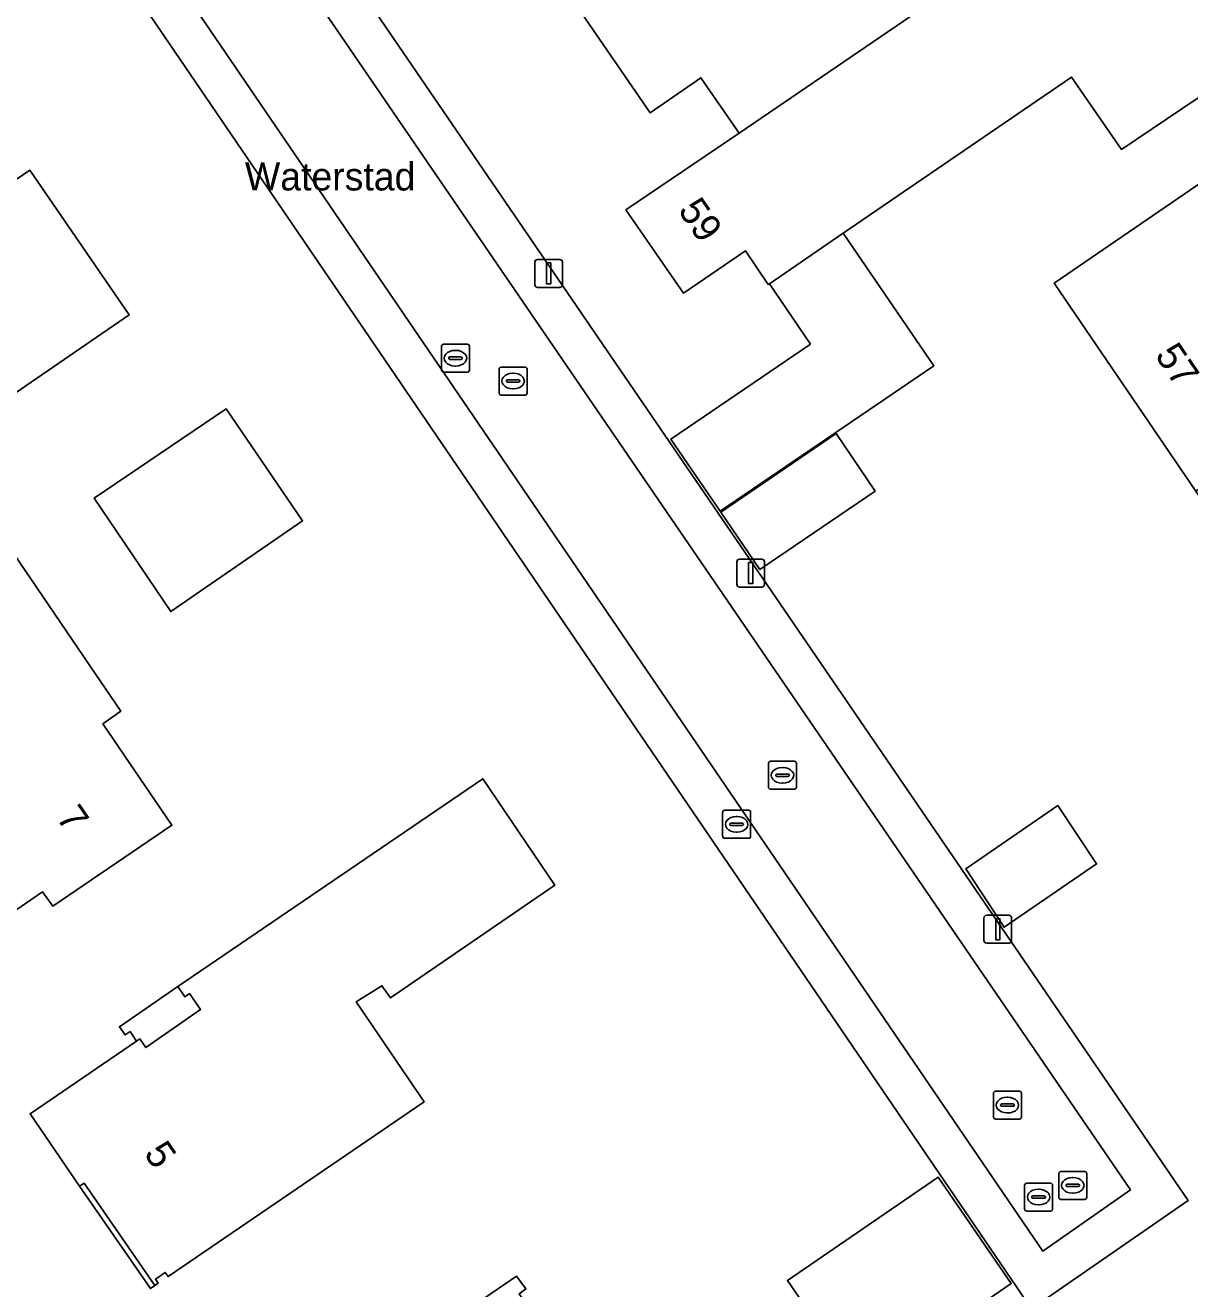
# Model space of a CAD drawing. Extents: x 155275 to 156265, y 382654 to 383635.
# Drawn here: x 155692.89 to 155734.53, y 383268.44 to 383313.6 of the extents above; entities that cross this region are included whole.
import ezdxf

# ---------------------------------------------------------------- set-up
doc = ezdxf.new("R2010")
doc.units = 0
for name, color, linetype in [('IMGEO_Brandkraan', 7, 'Continuous'), ('IMGEO_Erf', 7, 'Continuous'), ('IMGEO_Kolk', 7, 'Continuous'), ('IMGEO_Lichtmast', 7, 'Continuous'), ('IMGEO_Openbare_ruimte_label', 7, 'Continuous'), ('IMGEO_Pand', 7, 'Continuous'), ('IMGEO_Pand_nummerreeks', 7, 'Continuous'), ('IMGEO_Pand_overbouw', 7, 'Continuous'), ('IMGEO_Rijbaan_lokaal_open', 7, 'Continuous'), ('IMGEO_Rioolput', 7, 'Continuous'), ('IMGEO_Voetpad_open', 7, 'Continuous')]:
    doc.layers.add(name, color=color, linetype=linetype)

msp = doc.modelspace()

# ---------------------------------------------------------------- linework, layer by layer
at = {"layer": 'IMGEO_Brandkraan'}
for p, q in [((155717.827, 383284.614), (155717.827, 383285.466)), ((155717.902, 383285.54), (155718.754, 383285.54)), ((155718.315, 383285.32), (155718.34, 383285.32)), ((155718.828, 383285.466), (155718.828, 383284.614)), ((155718.086, 383285.034), (155718.086, 383285.046)), ((155718.524, 383284.997), (155718.126, 383284.997)), ((155718.129, 383285.083), (155718.527, 383285.083)), ((155718.57, 383285.046), (155718.57, 383285.034)), ((155718.754, 383284.54), (155717.902, 383284.54)), ((155718.338, 383284.76), (155718.313, 383284.76))]:
    msp.add_line(p, q, dxfattribs=at)
for points in [[(155717.827, 383284.614), (155717.827, 383285.466)], [(155717.902, 383285.54), (155718.754, 383285.54)], [(155718.828, 383285.466), (155718.828, 383284.614)], [(155718.754, 383284.54), (155717.902, 383284.54)]]:
    msp.add_lwpolyline(points, dxfattribs=at)
for centre, radius, start, end in [((155717.904, 383285.464), 0.0765, 91.552, 178.448), ((155717.904, 383285.464), 0.0765, 91.552, 178.448), ((155718.752, 383285.464), 0.0765, 1.552, 88.448), ((155718.752, 383285.464), 0.0765, 1.552, 88.448), ((155718.126, 383285.043), 0.0403, 85.8775, 175.7526), ((155718.123, 383285.033), 0.0366, 178.938, 274.7102), ((155718.527, 383285.04), 0.043, 264.8664, 352.4533), ((155718.531, 383285.045), 0.0386, 1.7309, 96.639), ((155717.904, 383284.616), 0.0765, 181.552, 268.448), ((155717.904, 383284.616), 0.0765, 181.552, 268.448), ((155718.752, 383284.616), 0.0765, 271.552, 358.448), ((155718.752, 383284.616), 0.0765, 271.552, 358.448)]:
    msp.add_arc(centre, radius, start, end, dxfattribs=at)
for centre, major_axis, ratio, start_param, end_param in [((155718.314, 383285.04), (-0.387, 0.002), 0.722429, 4.712389, 7.853982), ((155718.339, 383285.04), (-0.39, 0.002), 0.717154, 1.570796, 4.712389)]:
    msp.add_ellipse(centre, major_axis=major_axis, ratio=ratio, start_param=start_param, end_param=end_param, dxfattribs=at)
at = {"layer": 'IMGEO_Erf'}
for points in [[(155693.884, 383330.96), (155734.469, 383271.59), (155728.87, 383267.725), (155692.93, 383320.467), (155688.369, 383327.082)], [(155732.298, 383319.22), (155736.952, 383312.438), (155732.083, 383309.164), (155730.299, 383311.75), (155722.139, 383306.171), (155725.378, 383301.433), (155717.735, 383296.233), (155715.98, 383298.813), (155720.966, 383302.205), (155719.497, 383304.365), (155719.456, 383304.337), (155718.644, 383305.537), (155716.426, 383304.029), (155714.371, 383307.002), (155718.414, 383309.742), (155717.048, 383311.729), (155715.234, 383310.476), (155711.378, 383316.095)]]:
    msp.add_lwpolyline(points, dxfattribs=at)
for points in [[(155729.681, 383304.386), (155735.196, 383308.156), (155736.885, 383305.645), (155740.09, 383307.82), (155743.449, 383302.891), (155747.678, 383296.685), (155738.98, 383290.741), (155734.744, 383296.945)], [(155702.807, 383295.889), (155698.093, 383292.642), (155695.354, 383296.697), (155700.077, 383299.887)], [(155717.758, 383296.2), (155721.882, 383299.006), (155723.279, 383296.952), (155719.162, 383294.151)], [(155696.305, 383289.084), (155695.666, 383288.626), (155698.138, 383285.007), (155693.88, 383282.11), (155693.511, 383282.621), (155689.526, 383279.897), (155686.616, 383284.207), (155686.946, 383284.433), (155685.479, 383286.579), (155686.883, 383287.539), (155685.303, 383289.85), (155692.46, 383294.743), (155695.211, 383290.695)], [(155705.946, 383278.833), (155705.646, 383279.27), (155704.728, 383278.7), (155707.15, 383275.123), (155698.001, 383268.874), (155697.9, 383269.023), (155697.545, 383268.786), (155697.647, 383268.638), (155697.523, 383268.551), (155694.995, 383272.212), (155694.838, 383272.105), (155693.069, 383274.695), (155696.868, 383277.29), (155696.987, 383277.376), (155697.21, 383277.058), (155699.16, 383278.418), (155698.76, 383278.992), (155698.596, 383278.878), (155698.345, 383279.237), (155709.258, 383286.667), (155711.833, 383282.866)], [(155726.527, 383283.449), (155729.81, 383285.709), (155731.194, 383283.622), (155727.891, 383281.36)], [(155728.147, 383268.629), (155707.057, 383254.188), (155704.717, 383257.623), (155705.227, 383257.972), (155704.294, 383259.337), (155704.145, 383259.236), (155701.658, 383262.871), (155710.458, 383268.888), (155710.791, 383268.434), (155710.55, 383268.256), (155713.354, 383264.091), (155713.617, 383264.267), (155717.71, 383267.089), (155718.705, 383265.728), (155721.105, 383267.326), (155720.14, 383268.738), (155725.534, 383272.422)]]:
    msp.add_lwpolyline(points, close=True, dxfattribs=at)
at = {"layer": 'IMGEO_Kolk'}
for p, q in [((155709.835, 383300.459), (155709.835, 383301.311)), ((155709.91, 383301.385), (155710.762, 383301.385)), ((155710.323, 383301.165), (155710.348, 383301.165)), ((155710.836, 383301.311), (155710.836, 383300.459)), ((155710.094, 383300.879), (155710.094, 383300.891)), ((155710.532, 383300.842), (155710.134, 383300.842)), ((155710.137, 383300.928), (155710.535, 383300.928)), ((155710.578, 383300.891), (155710.578, 383300.879)), ((155710.762, 383300.385), (155709.91, 383300.385)), ((155710.346, 383300.605), (155710.321, 383300.605)), ((155719.465, 383286.367), (155719.465, 383287.219)), ((155719.54, 383287.293), (155720.392, 383287.293)), ((155719.953, 383287.073), (155719.978, 383287.073)), ((155720.466, 383287.219), (155720.466, 383286.367)), ((155719.724, 383286.787), (155719.724, 383286.799)), ((155720.162, 383286.75), (155719.764, 383286.75)), ((155719.767, 383286.836), (155720.165, 383286.836)), ((155720.208, 383286.799), (155720.208, 383286.787)), ((155720.392, 383286.293), (155719.54, 383286.293)), ((155719.976, 383286.513), (155719.951, 383286.513)), ((155727.507, 383274.576), (155727.507, 383275.428)), ((155727.582, 383275.502), (155728.434, 383275.502)), ((155728.508, 383275.428), (155728.508, 383274.576)), ((155727.766, 383274.996), (155727.766, 383275.008)), ((155728.204, 383274.959), (155727.806, 383274.959)), ((155727.809, 383275.045), (155728.207, 383275.045)), ((155727.995, 383275.282), (155728.02, 383275.282)), ((155728.25, 383275.008), (155728.25, 383274.996)), ((155728.434, 383274.502), (155727.582, 383274.502)), ((155728.018, 383274.722), (155727.993, 383274.722))]:
    msp.add_line(p, q, dxfattribs=at)
for points in [[(155709.835, 383300.459), (155709.835, 383301.311)], [(155709.91, 383301.385), (155710.762, 383301.385)], [(155710.836, 383301.311), (155710.836, 383300.459)], [(155710.762, 383300.385), (155709.91, 383300.385)], [(155719.465, 383286.367), (155719.465, 383287.219)], [(155719.54, 383287.293), (155720.392, 383287.293)], [(155720.466, 383287.219), (155720.466, 383286.367)], [(155720.392, 383286.293), (155719.54, 383286.293)], [(155727.507, 383274.576), (155727.507, 383275.428)], [(155727.582, 383275.502), (155728.434, 383275.502)], [(155728.508, 383275.428), (155728.508, 383274.576)], [(155728.434, 383274.502), (155727.582, 383274.502)]]:
    msp.add_lwpolyline(points, dxfattribs=at)
for centre, radius, start, end in [((155709.912, 383301.309), 0.0765, 91.552, 178.448), ((155709.912, 383301.309), 0.0765, 91.552, 178.448), ((155710.76, 383301.309), 0.0765, 1.552, 88.448), ((155710.76, 383301.309), 0.0765, 1.552, 88.448), ((155710.134, 383300.888), 0.0403, 85.8775, 175.7526), ((155710.131, 383300.878), 0.0366, 178.938, 274.7102), ((155710.535, 383300.885), 0.043, 264.8664, 352.4533), ((155710.539, 383300.89), 0.0386, 1.7309, 96.639), ((155709.912, 383300.461), 0.0765, 181.552, 268.448), ((155709.912, 383300.461), 0.0765, 181.552, 268.448), ((155710.76, 383300.461), 0.0765, 271.552, 358.448), ((155710.76, 383300.461), 0.0765, 271.552, 358.448), ((155719.542, 383287.217), 0.0765, 91.552, 178.448), ((155719.542, 383287.217), 0.0765, 91.552, 178.448), ((155720.39, 383287.217), 0.0765, 1.552, 88.448), ((155720.39, 383287.217), 0.0765, 1.552, 88.448), ((155719.764, 383286.796), 0.0403, 85.8775, 175.7526), ((155719.761, 383286.786), 0.0366, 178.938, 274.7102), ((155720.165, 383286.793), 0.043, 264.8664, 352.4533), ((155720.169, 383286.798), 0.0386, 1.7309, 96.639), ((155719.542, 383286.369), 0.0765, 181.552, 268.448), ((155719.542, 383286.369), 0.0765, 181.552, 268.448), ((155720.39, 383286.369), 0.0765, 271.552, 358.448), ((155720.39, 383286.369), 0.0765, 271.552, 358.448), ((155727.584, 383275.426), 0.0765, 91.552, 178.448), ((155727.584, 383275.426), 0.0765, 91.552, 178.448), ((155728.432, 383275.426), 0.0765, 1.552, 88.448), ((155728.432, 383275.426), 0.0765, 1.552, 88.448), ((155727.806, 383275.005), 0.0403, 85.8775, 175.7526), ((155727.803, 383274.995), 0.0366, 178.938, 274.7102), ((155728.207, 383275.002), 0.043, 264.8664, 352.4533), ((155728.211, 383275.007), 0.0386, 1.7309, 96.639), ((155727.584, 383274.578), 0.0765, 181.552, 268.448), ((155727.584, 383274.578), 0.0765, 181.552, 268.448), ((155728.432, 383274.578), 0.0765, 271.552, 358.448), ((155728.432, 383274.578), 0.0765, 271.552, 358.448)]:
    msp.add_arc(centre, radius, start, end, dxfattribs=at)
for centre, major_axis, ratio, start_param, end_param in [((155710.322, 383300.885), (-0.387, 0.002), 0.722429, 4.712389, 7.853982), ((155710.347, 383300.885), (-0.39, 0.002), 0.717154, 1.570796, 4.712389), ((155719.952, 383286.793), (-0.387, 0.002), 0.722429, 4.712389, 7.853982), ((155719.977, 383286.793), (-0.39, 0.002), 0.717154, 1.570796, 4.712389), ((155727.994, 383275.002), (-0.387, 0.002), 0.722429, 4.712389, 7.853982), ((155728.019, 383275.002), (-0.39, 0.002), 0.717154, 1.570796, 4.712389)]:
    msp.add_ellipse(centre, major_axis=major_axis, ratio=ratio, start_param=start_param, end_param=end_param, dxfattribs=at)
at = {"layer": 'IMGEO_Lichtmast'}
for p, q in [((155711.212, 383305.23), (155712.002, 383305.23)), ((155712.002, 383305.23), (155711.212, 383305.23)), ((155711.112, 383304.33), (155711.112, 383305.13)), ((155711.112, 383305.13), (155711.112, 383304.33)), ((155712.102, 383305.13), (155712.102, 383304.33)), ((155712.102, 383304.33), (155712.102, 383305.13)), ((155712.002, 383304.23), (155711.212, 383304.23)), ((155711.212, 383304.23), (155712.002, 383304.23)), ((155718.334, 383293.618), (155718.334, 383294.418)), ((155718.334, 383294.418), (155718.334, 383293.618)), ((155718.434, 383294.518), (155719.224, 383294.518)), ((155719.224, 383294.518), (155718.434, 383294.518)), ((155719.324, 383294.418), (155719.324, 383293.618)), ((155719.324, 383293.618), (155719.324, 383294.418)), ((155719.224, 383293.518), (155718.434, 383293.518)), ((155718.434, 383293.518), (155719.224, 383293.518)), ((155727.168, 383280.89), (155727.168, 383281.69)), ((155727.168, 383281.69), (155727.168, 383280.89)), ((155727.268, 383281.79), (155728.058, 383281.79)), ((155728.058, 383281.79), (155727.268, 383281.79)), ((155728.158, 383281.69), (155728.158, 383280.89)), ((155728.158, 383280.89), (155728.158, 383281.69)), ((155728.058, 383280.79), (155727.268, 383280.79)), ((155727.268, 383280.79), (155728.058, 383280.79))]:
    msp.add_line(p, q, dxfattribs=at)
for points in [[(155711.532, 383305.105), (155711.682, 383305.105), (155711.682, 383304.355), (155711.532, 383304.355), (155711.532, 383305.105)], [(155718.754, 383294.393), (155718.904, 383294.393), (155718.904, 383293.643), (155718.754, 383293.643), (155718.754, 383294.393)], [(155727.588, 383281.665), (155727.738, 383281.665), (155727.738, 383280.915), (155727.588, 383280.915), (155727.588, 383281.665)]]:
    msp.add_lwpolyline(points, dxfattribs=at)
for centre, start, end in [((155711.212, 383305.13), 90, 180), ((155711.212, 383305.13), 90, 180), ((155712.002, 383305.13), 0, 90), ((155712.002, 383305.13), 360, 90), ((155711.212, 383304.33), 180, 270), ((155711.212, 383304.33), 180, 270), ((155712.002, 383304.33), 270, 0), ((155712.002, 383304.33), 270, 0), ((155718.434, 383294.418), 90, 180), ((155718.434, 383294.418), 90, 180), ((155719.224, 383294.418), 0, 90), ((155719.224, 383294.418), 360, 90), ((155718.434, 383293.618), 180, 270), ((155718.434, 383293.618), 180, 270), ((155719.224, 383293.618), 270, 0), ((155719.224, 383293.618), 270, 0), ((155727.268, 383281.69), 90, 180), ((155727.268, 383281.69), 90, 180), ((155728.058, 383281.69), 0, 90), ((155728.058, 383281.69), 360, 90), ((155727.268, 383280.89), 180, 270), ((155727.268, 383280.89), 180, 270), ((155728.058, 383280.89), 270, 0), ((155728.058, 383280.89), 270, 0)]:
    msp.add_arc(centre, 0.1, start, end, dxfattribs=at)
at = {"layer": 'IMGEO_Pand'}
for points in [[(155731.476, 383318.658), (155730.513, 383320.077), (155731.339, 383320.63), (155727.941, 383325.612), (155722.728, 383322.057), (155724.373, 383319.645), (155716.516, 383314.29), (155714.029, 383317.915), (155711.378, 383316.095), (155715.234, 383310.476), (155717.048, 383311.729), (155718.414, 383309.742)], [(155730.299, 383311.75), (155732.083, 383309.164), (155736.952, 383312.438), (155732.298, 383319.22), (155731.476, 383318.658), (155718.414, 383309.742), (155714.371, 383307.002), (155716.426, 383304.029), (155718.644, 383305.537), (155719.456, 383304.337), (155719.497, 383304.365), (155722.139, 383306.171)], [(155740.09, 383307.82), (155736.885, 383305.645), (155735.196, 383308.156), (155729.681, 383304.386), (155734.744, 383296.945), (155743.449, 383302.891)], [(155725.378, 383301.433), (155722.139, 383306.171), (155719.497, 383304.365), (155720.966, 383302.205), (155715.98, 383298.813), (155717.735, 383296.233)], [(155695.354, 383296.697), (155698.093, 383292.642), (155702.807, 383295.889), (155700.077, 383299.887)], [(155723.279, 383296.952), (155721.882, 383299.006), (155717.758, 383296.2), (155719.162, 383294.151)], [(155689.526, 383279.897), (155693.511, 383282.621), (155693.88, 383282.11), (155698.138, 383285.007), (155695.666, 383288.626), (155696.305, 383289.084), (155695.211, 383290.695), (155692.46, 383294.743), (155685.303, 383289.85), (155686.883, 383287.539), (155685.479, 383286.579), (155686.946, 383284.433), (155686.616, 383284.207)], [(155694.838, 383272.105), (155694.995, 383272.212), (155697.523, 383268.551), (155697.647, 383268.638), (155697.545, 383268.786), (155697.9, 383269.023), (155698.001, 383268.874), (155707.15, 383275.123), (155704.728, 383278.7), (155705.646, 383279.27), (155705.946, 383278.833), (155711.833, 383282.866), (155709.258, 383286.667), (155698.345, 383279.237), (155698.596, 383278.878), (155698.76, 383278.992), (155699.16, 383278.418), (155697.21, 383277.058), (155696.987, 383277.376), (155696.868, 383277.29), (155693.069, 383274.695)], [(155731.194, 383283.622), (155729.81, 383285.709), (155726.527, 383283.449), (155727.891, 383281.36)], [(155704.717, 383257.623), (155707.057, 383254.188), (155728.147, 383268.629), (155725.534, 383272.422), (155720.14, 383268.738), (155721.105, 383267.326), (155718.705, 383265.728), (155717.71, 383267.089), (155713.617, 383264.267), (155713.354, 383264.091), (155710.55, 383268.256), (155710.791, 383268.434), (155710.458, 383268.888), (155701.658, 383262.871), (155704.145, 383259.236), (155704.294, 383259.337), (155705.227, 383257.972)]]:
    msp.add_lwpolyline(points, close=True, dxfattribs=at)
at = {"layer": 'IMGEO_Pand_overbouw'}
for points in [[(155690.77, 383299.247), (155696.611, 383303.246), (155693.054, 383308.422), (155688.955, 383305.631), (155691.937, 383301.295), (155690.188, 383300.097)], [(155696.868, 383277.29), (155696.987, 383277.376), (155697.21, 383277.058), (155699.16, 383278.418), (155698.76, 383278.992), (155698.596, 383278.878), (155698.345, 383279.237), (155696.263, 383277.806), (155696.465, 383277.51), (155696.642, 383277.631)], [(155694.838, 383272.105), (155697.367, 383268.444), (155697.523, 383268.551), (155694.995, 383272.212)]]:
    msp.add_lwpolyline(points, close=True, dxfattribs=at)
at = {"layer": 'IMGEO_Rijbaan_lokaal_open'}
msp.add_lwpolyline([(155689.962, 383327.416), (155729.272, 383269.785), (155732.407, 383271.977), (155693.039, 383329.522)], dxfattribs=at)
at = {"layer": 'IMGEO_Rioolput'}
for p, q in [((155707.774, 383301.276), (155707.774, 383302.128)), ((155707.849, 383302.202), (155708.701, 383302.202)), ((155708.262, 383301.982), (155708.287, 383301.982)), ((155708.775, 383302.128), (155708.775, 383301.276)), ((155708.033, 383301.696), (155708.033, 383301.708)), ((155708.471, 383301.659), (155708.073, 383301.659)), ((155708.076, 383301.745), (155708.474, 383301.745)), ((155708.517, 383301.708), (155708.517, 383301.696)), ((155708.701, 383301.202), (155707.849, 383301.202)), ((155708.285, 383301.422), (155708.26, 383301.422)), ((155729.919, 383272.633), (155730.771, 383272.633)), ((155728.696, 383272.215), (155729.548, 383272.215)), ((155729.844, 383271.707), (155729.844, 383272.559)), ((155730.146, 383272.176), (155730.544, 383272.176)), ((155730.332, 383272.413), (155730.357, 383272.413)), ((155730.845, 383272.559), (155730.845, 383271.707)), ((155728.621, 383271.289), (155728.621, 383272.141)), ((155728.88, 383271.709), (155728.88, 383271.721)), ((155728.923, 383271.758), (155729.321, 383271.758)), ((155729.109, 383271.995), (155729.134, 383271.995)), ((155729.364, 383271.721), (155729.364, 383271.709)), ((155729.622, 383272.141), (155729.622, 383271.289)), ((155730.103, 383272.127), (155730.103, 383272.139)), ((155730.541, 383272.09), (155730.143, 383272.09)), ((155730.355, 383271.853), (155730.33, 383271.853)), ((155730.587, 383272.139), (155730.587, 383272.127)), ((155729.318, 383271.672), (155728.92, 383271.672)), ((155729.132, 383271.435), (155729.107, 383271.435)), ((155730.771, 383271.633), (155729.919, 383271.633)), ((155729.548, 383271.215), (155728.696, 383271.215))]:
    msp.add_line(p, q, dxfattribs=at)
for points in [[(155707.774, 383301.276), (155707.774, 383302.128)], [(155707.849, 383302.202), (155708.701, 383302.202)], [(155708.775, 383302.128), (155708.775, 383301.276)], [(155708.701, 383301.202), (155707.849, 383301.202)], [(155729.919, 383272.633), (155730.771, 383272.633)], [(155728.696, 383272.215), (155729.548, 383272.215)], [(155729.844, 383271.707), (155729.844, 383272.559)], [(155730.845, 383272.559), (155730.845, 383271.707)], [(155728.621, 383271.289), (155728.621, 383272.141)], [(155729.622, 383272.141), (155729.622, 383271.289)], [(155730.771, 383271.633), (155729.919, 383271.633)], [(155729.548, 383271.215), (155728.696, 383271.215)]]:
    msp.add_lwpolyline(points, dxfattribs=at)
for centre, radius, start, end in [((155707.851, 383302.126), 0.0765, 91.552, 178.448), ((155707.851, 383302.126), 0.0765, 91.552, 178.448), ((155708.699, 383302.126), 0.0765, 1.552, 88.448), ((155708.699, 383302.126), 0.0765, 1.552, 88.448), ((155708.073, 383301.705), 0.0403, 85.8775, 175.7526), ((155708.07, 383301.695), 0.0366, 178.938, 274.7102), ((155708.474, 383301.702), 0.043, 264.8664, 352.4533), ((155708.478, 383301.707), 0.0386, 1.7309, 96.639), ((155707.851, 383301.278), 0.0765, 181.552, 268.448), ((155707.851, 383301.278), 0.0765, 181.552, 268.448), ((155708.699, 383301.278), 0.0765, 271.552, 358.448), ((155708.699, 383301.278), 0.0765, 271.552, 358.448), ((155729.921, 383272.557), 0.0765, 91.552, 178.448), ((155729.921, 383272.557), 0.0765, 91.552, 178.448), ((155730.769, 383272.557), 0.0765, 1.552, 88.448), ((155730.769, 383272.557), 0.0765, 1.552, 88.448), ((155728.698, 383272.139), 0.0765, 91.552, 178.448), ((155728.698, 383272.139), 0.0765, 91.552, 178.448), ((155729.546, 383272.139), 0.0765, 1.552, 88.448), ((155729.546, 383272.139), 0.0765, 1.552, 88.448), ((155730.143, 383272.136), 0.0403, 85.8775, 175.7526), ((155730.548, 383272.138), 0.0386, 1.7309, 96.639), ((155728.92, 383271.718), 0.0403, 85.8775, 175.7526), ((155729.325, 383271.72), 0.0386, 1.7309, 96.639), ((155730.14, 383272.126), 0.0366, 178.938, 274.7102), ((155730.544, 383272.133), 0.043, 264.8664, 352.4533), ((155728.698, 383271.291), 0.0765, 181.552, 268.448), ((155728.698, 383271.291), 0.0765, 181.552, 268.448), ((155728.917, 383271.708), 0.0366, 178.938, 274.7102), ((155729.321, 383271.715), 0.043, 264.8664, 352.4533), ((155729.546, 383271.291), 0.0765, 271.552, 358.448), ((155729.546, 383271.291), 0.0765, 271.552, 358.448), ((155729.921, 383271.709), 0.0765, 181.552, 268.448), ((155729.921, 383271.709), 0.0765, 181.552, 268.448), ((155730.769, 383271.709), 0.0765, 271.552, 358.448), ((155730.769, 383271.709), 0.0765, 271.552, 358.448)]:
    msp.add_arc(centre, radius, start, end, dxfattribs=at)
for centre, major_axis, ratio, start_param, end_param in [((155708.261, 383301.702), (-0.387, 0.002), 0.722429, 4.712389, 7.853982), ((155708.286, 383301.702), (-0.39, 0.002), 0.717154, 1.570796, 4.712389), ((155730.331, 383272.133), (-0.387, 0.002), 0.722429, 4.712389, 7.853982), ((155730.356, 383272.133), (-0.39, 0.002), 0.717154, 1.570796, 4.712389), ((155729.108, 383271.715), (-0.387, 0.002), 0.722429, 4.712389, 7.853982), ((155729.133, 383271.715), (-0.39, 0.002), 0.717154, 1.570796, 4.712389)]:
    msp.add_ellipse(centre, major_axis=major_axis, ratio=ratio, start_param=start_param, end_param=end_param, dxfattribs=at)
at = {"layer": 'IMGEO_Voetpad_open'}
for points in [[(155688.369, 383327.082), (155692.93, 383320.467), (155728.87, 383267.725), (155734.469, 383271.59), (155693.884, 383330.96)], [(155693.039, 383329.522), (155732.407, 383271.977), (155729.272, 383269.785), (155689.962, 383327.416)]]:
    msp.add_lwpolyline(points, dxfattribs=at)

# ---------------------------------------------------------------- texts
at = {"layer": 'IMGEO_Openbare_ruimte_label'}
msp.add_text('Waterstad', height=1, dxfattribs=at).set_placement((155700.748, 383307.697))
at = {"layer": 'IMGEO_Pand_nummerreeks'}
for s, rotation, p in [('59', 304.6523, (155716.206, 383306.985)), ('57', 304.0736, (155733.259, 383301.804)), ('7', 304.3431, (155693.981, 383285.278)), ('5', 304.4896, (155697.112, 383273.266))]:
    msp.add_text(s, height=1, rotation=rotation, dxfattribs=at).set_placement(p)

doc.saveas('drawing.dxf')
